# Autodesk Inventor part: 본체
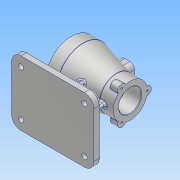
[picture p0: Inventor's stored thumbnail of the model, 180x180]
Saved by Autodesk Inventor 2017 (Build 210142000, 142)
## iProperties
Part Number: 본체
Material: 알루미늄 6061
Document SubType Name: Modeling
Designer: user
Density: 2.7 g/cm^3
Appearance: 알루미늄 - 평지
Mass: 1223.12 g
Surface Area: 899.626 cm^2
Volume: 453.008 cm^3
Author: user
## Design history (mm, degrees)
sketch "스케치1"
  geometry: L1 (-50, 0)-(50, 0); L2 (-50, 45)-(-30.413, 45); L3 (-29.602, 44.888)-(26.602, 29.112); L4 (27.413, 29)-(50, 29); L5 (50, 29)-(50, 19); L6 (50, 19)-(23, 19); L7 (20, 22)-(20, 22); L8 (17, 25)-(-24, 25); L9 (-27, 28)-(-27, 28); L10 (-30, 31)-(-50, 31); L11 (-50, 31)-(-50, 45); A1 r 3 centre (-30, 28) between (-27, 28) and (-30, 31); A2 r 3 centre (-24, 28) between (-27, 28) and (-24, 25); A3 r 3 centre (17, 22) between (20, 22) and (17, 25); A4 r 3 centre (23, 22) between (20, 22) and (23, 19); A5 r 3 centre (-30.413, 42) between (-29.602, 44.888) and (-30.413, 45); A6 r 3 centre (27.413, 32) between (26.602, 29.112) and (27.413, 29); 7 further points
  constraints: 22 end point, 12 point on circle, 12 tangent, 10 point on line, 7 perpendicular, 6 centre point, 5 equal radius, 2 horizontal, 2 vertical alignment, 1 coincident, 1 midpoint, 1 parallel
  dimensions: "d0" = 100 distance of L1.start L1.end; "d1" = 20 distance of L2.start point (-30, 45); "d2" = 23 distance of point (27, 29) L4.end; "d3" = 90 diameter of L2 L1; "d4" = 62 diameter of L10 L1; "d5" = 23 distance of point (-27, 31) L10.end; "d6" = 47 distance of point (20, 25) point (-27, 25); "d7" = 50 diameter of L8 L1; "d8" = 38 diameter of L6 L1; "d9" = 58 diameter of L4 L1; "d10" = 3 radius of A1
revolve "회전1" sketch "스케치1" stored, may be unused: angle "d11" = 90 deg
sketch "스케치2" dims "d12" = 80
  geometry: L1 (0, 40)-(34.641, 20); L2 (34.641, 20)-(34.641, -20); L3 (34.641, -20)-(0, -40); L4 (0, -40)-(-34.641, -20); L5 (-34.641, -20)-(-34.641, 20); L6 (-34.641, 20)-(0, 40); C1 r 31 at (0, 0) reference; 8 further points
  constraints: 12 end point, 8 coincident, 1 vertical, 1 vertical alignment, 15 other
hole "구멍1" sketch "스케치2" at (0, 40), (34.641, 20), (34.641, -20), (0, -40), (-34.641, -20), (-34.641, 20) diameter "d13" = 3.242; stored, may be unused: countersink angle "d17" = 90 deg, drill point angle "d19" = 118 deg; dims "d14" = 9, "d15" = 4, "d16" = 2, "d18" = 11
sketch "스케치3"
  geometry: L1 (0, 29)-(25.115, -14.5); L2 (25.115, -14.5)-(-25.115, -14.5); L3 (-25.115, -14.5)-(0, 29); C1 r 7 at (0, 29); C2 r 7 at (25.115, -14.5); C3 r 7 at (-25.115, -14.5); 2 further points
  constraints: 6 end point, 4 coincident, 3 centre point, 1 horizontal, 1 vertical alignment, 8 other
  dimensions: "d20" = 14 diameter of C2; "d22" = 14 diameter of C1; "d23" = 14 diameter of C3
extrude "돌출1" join sketch "스케치3" distance "d24" = 15; taper "d25" = 0 deg
sketch "스케치4"
  geometry: A1 r 7 centre (25.115, -43.5) between (20.909, -49.095) and (27.858, -37.06) reference; A2 r 7 centre (0, 0) between (6.949, -0.845) and (-6.949, -0.845) reference; A3 r 7 centre (-25.115, -43.5) between (-27.858, -37.06) and (-20.909, -49.095) reference; 3 further points
  constraints: 3 coincident
hole "구멍2" sketch "스케치4" at (0, 0), (-25.115, -43.5), (25.115, -43.5) diameter "d26" = 3.242; stored, may be unused: countersink angle "d30" = 90 deg, drill point angle "d32" = 118 deg; dims "d27" = 9, "d28" = 4, "d29" = 2, "d31" = 11
node "작업 평면1"
sketch "스케치5"
  geometry: L1 (-4.5, -12.5)-(4.5, -12.5); L2 (12.5, -4.5)-(12.5, 4.5); L3 (4.5, 12.5)-(-4.5, 12.5); L4 (-12.5, 4.5)-(-12.5, -4.5); L5 (-12.5, -12.5)-(12.5, 12.5); L6 (12.5, -12.5)-(-12.5, 12.5); L7 (50, 45)-(50, -45) reference; A1 r 8 centre (-4.5, -4.5) between (-12.5, -4.5) and (-4.5, -12.5); A2 r 8 centre (-4.5, 4.5) between (-4.5, 12.5) and (-12.5, 4.5); A3 r 8 centre (4.5, 4.5) between (12.5, 4.5) and (4.5, 12.5); A4 r 8 centre (4.5, -4.5) between (4.5, -12.5) and (12.5, -4.5); 3 further points
  constraints: 12 end point, 8 point on circle, 8 point on line, 8 tangent, 4 centre point, 3 equal radius, 3 midpoint, 2 parallel, 1 coincident, 1 horizontal, 1 perpendicular
  dimensions: "d34" = 25 distance of L6.end L5.end; "d35" = 25 distance of L5.end L6.start; "d36" = 8 radius of A1; "d37" = 50 distance from line of L7 point (0, 0)
extrude "돌출2" join sketch "스케치5" stored distance "d38" = 15; taper "d39" = 0 deg
sketch "스케치6"
  geometry: 2 further points
  constraints: 1 coincident
hole "구멍3" sketch "스케치6" at (0, 0) diameter "d40" = 15; stored, may be unused: countersink angle "d44" = 90 deg, drill point angle "d46" = 118 deg; dims "d41" = 9, "d42" = 4, "d43" = 2, "d45" = 15
node "작업 평면2"
sketch "스케치7"
  geometry: L1 (-54, 55)-(54, 55); L2 (70, 39)-(70, -39); L3 (54, -55)-(-54, -55); L4 (-70, -39)-(-70, 39); L5 (-70, 55)-(70, -55); L6 (70, 55)-(-70, -55); A1 r 16 centre (54, 39) between (70, 39) and (54, 55); A2 r 16 centre (-54, 39) between (-54, 55) and (-70, 39); A3 r 16 centre (-54, -39) between (-70, -39) and (-54, -55); A4 r 16 centre (54, -39) between (54, -55) and (70, -39); 1 further point
  constraints: 12 end point, 8 point on circle, 8 point on line, 8 tangent, 4 centre point, 3 equal radius, 2 midpoint, 2 parallel, 1 horizontal, 1 perpendicular
  dimensions: "d48" = 140 distance of L5.end L6.end; "d49" = 110 distance of L6.start L5.end; "d50" = 16 radius of A1
extrude "돌출3" join sketch "스케치7" distance "d51" = 12; taper "d52" = 0 deg
sketch "스케치8"
  geometry: L1 (54, 55)-(-54, 55) reference; L2 (-70, 39)-(-70, -39) reference; 5 further points
  constraints: 2 horizontal alignment, 2 vertical alignment
  dimensions: "d53" = 16 distance from line of L2 point (-54, 39); "d54" = 108 distance of point (54, 39) point (-54, 39); "d55" = 16 distance from line of L1 point (-54, 39); "d56" = 78 distance of point (-54, -39) point (-54, 39)
hole "구멍4" sketch "스케치8" at (-54, 39), (54, 39), (54, -39), (-54, -39) diameter "d57" = 9; stored, may be unused: countersink angle "d61" = 90 deg, drill point angle "d63" = 118 deg; dims "d58" = 9, "d59" = 18, "d60" = 2, "d62" = 15
sketch "스케치9"
  geometry: L1 (-70, 39)-(-70, -39) reference; L2 (-37, 4)-(37, 4); L3 (37, 4)-(37, -4); L4 (37, -4)-(-37, -4); L5 (-37, -4)-(-37, 4); L6 (-37, 4)-(37, -4); L7 (37, 4)-(-37, -4); 3 further points
  constraints: 12 end point, 3 midpoint, 2 parallel, 1 coincident, 1 horizontal, 1 perpendicular
  dimensions: "d64" = 74 distance of L3.end L4.end; "d65" = 8 distance of L2.end L3.end; "d66" = 33 distance between parallel lines of L5 L1
extrude "돌출4" join sketch "스케치9" stored distance "d67" = 12; taper "d68" = 0 deg
sketch "스케치10"
  geometry: L1 (45, 7.5)-(23.848, 7.5) reference; L2 (23.848, -7.5)-(45, -7.5) reference; L3 (45, -7.5)-(45, -12.5) reference; L4 (45, -12.5)-(34.377, -12.5) reference; L5 (-36.36, -4)-(-70, -4) reference; L6 (-70, -4)-(-70, -55) reference; L7 (-70, -55)-(-82, -55) reference; L8 (-82, -55)-(-82, 55) reference; L9 (-82, 55)-(-70, 55) reference; L10 (-70, 55)-(-70, 4) reference; L11 (-70, 4)-(-36.36, 4) reference; L12 (34.377, 12.5)-(45, 12.5) reference; L13 (45, 12.5)-(45, 7.5) reference; L14 (-70, -24)-(-30.278, -20.525); L15 (-30.278, 20.525)-(-70, 24); A1 r 25 centre (0, 0) between (23.848, 7.5) and (23.848, -7.5) reference; A2 r 36.579 centre (0, 0) between (-36.36, -4) and (34.377, -12.5) reference; A3 r 36.579 centre (0, 0) between (34.377, 12.5) and (-36.36, 4) reference; 1 further point
  constraints: 4 end point, 2 point on circle, 2 point on line
  dimensions: "d69" = 24 vertical distance of point (0, 0) L14.start; "d70" = 24 vertical distance of L15.end point (0, 0); "d71" = 95 deg angle of L6 L14; "d73" = 95 deg angle of L10 L15
  node "절단 모서리 투영1"
feature "리브1" dims "d74" = 1, "d75" = 8, "d76" = 0, "d77" = 0, "d78" = 1, "d79" = 1
feature "리브2" dims "d80" = 1, "d81" = 8, "d82" = 0, "d83" = 0, "d84" = 1, "d85" = 1
fillet "모깎기1" dims "d86" = 3
fillet "모깎기2" dims "d87" = 1
chamfer "모따기1" distance "d88" = 1; stored, may be unused: second distance "d89" = 2, angle "d90" = 45 deg
sketch "스케치11"
  geometry: L1 (-54, -55)-(54, -55) reference; 2 further points
  constraints: 1 vertical alignment, 1 other
  dimensions: "d91" = 15 distance from line of point (0, -40) L1
feature "엠보싱1" sketch "스케치11" dims "d0" = 100, "d1" = 20, "d2" = 23, "d3" = 90, "d4" = 62, "d5" = 23, "d6" = 47, "d7" = 50, "d8" = 38, "d9" = 58, "d10" = 3, "d92" = 0.5, "d93" = 0
node "솔리드1"
other parameters: "d33" = 45, "d47" = -82
